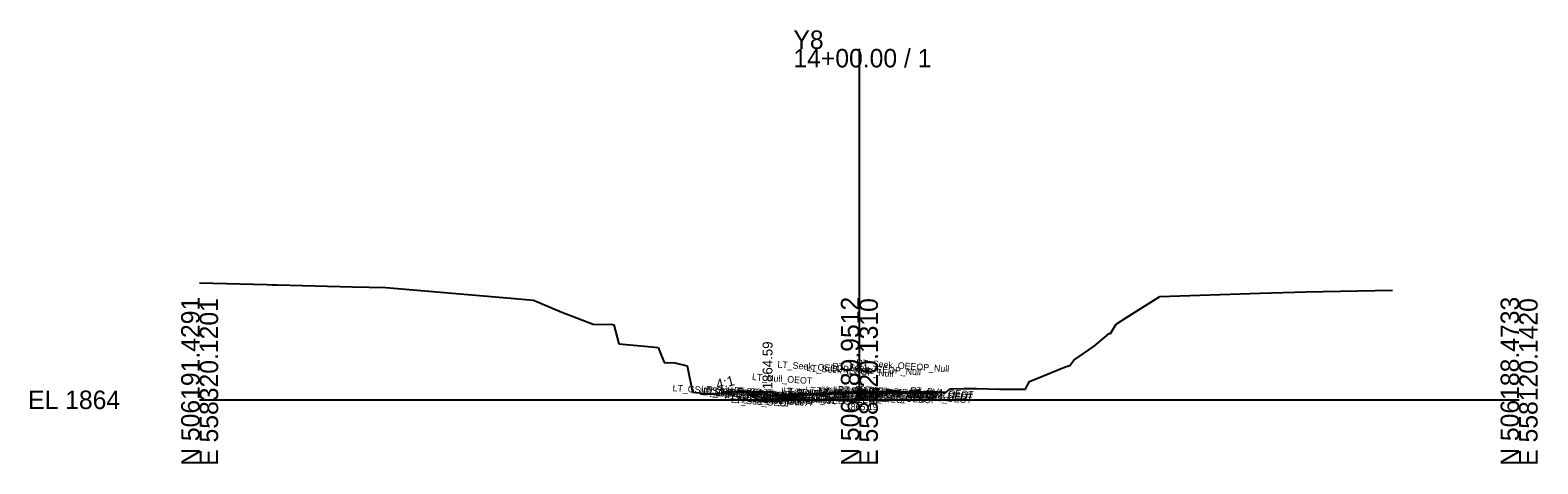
# Model space of a CAD drawing. Extents: x -26 to 203, y -10 to 8070.
# Drawn here: x -25.7 to 202.8, y 3990.3 to 4056 of the extents above; entities that cross this region are included whole.
import ezdxf

# ---------------------------------------------------------------- set-up
doc = ezdxf.new("R2010")
doc.units = 0
for name, color, linetype in [('Default', 7, 'Continuous'), ('Exist Cross Section Cell', 7, 'Continuous'), ('Exist XS Center Line Elevation Label', 7, 'Continuous'), ('Exist XS Ground Line', 7, 'Continuous'), ('Prop CMT Conc Surface', 7, 'Continuous'), ('Prop CMT Concrete Structures', 7, 'Continuous'), ('Prop CMT Pvmt Course 1', 7, 'Continuous'), ('Prop CMT Pvmt Course 1 CG', 7, 'Continuous'), ('Prop CMT Pvmt Course 2', 7, 'Continuous'), ('Prop CMT Pvmt Course 3', 7, 'Continuous'), ('Prop CMT Pvmt Surface', 7, 'Continuous'), ('Prop CMT Slope Grass', 7, 'Continuous'), ('Prop CMT Subgrade Earthwork', 7, 'Continuous'), ('Prop XS Earthwork Shape', 7, 'Continuous'), ('Prop XS Hydro Elevations', 7, 'Continuous'), ('Prop XS Side Slope Text', 7, 'Continuous'), ('Typical Text Grade Point CELL', 7, 'Continuous')]:
    doc.layers.add(name, color=color, linetype=linetype)

msp = doc.modelspace()

# ---------------------------------------------------------------- linework, layer by layer
at = {"layer": 'Exist Cross Section Cell'}
for p, q in [((100, 4000), (100, 4053.15)), ((0, 4000), (100, 4000)), ((100, 4000), (200, 4000))]:
    msp.add_line(p, q, dxfattribs=at)
at = {"layer": 'Exist XS Ground Line'}
for p, q in [((0, 4017.72), (10.19, 4017.45)), ((10.19, 4017.45), (10.97, 4017.44)), ((10.97, 4017.44), (11.82, 4017.4)), ((11.82, 4017.4), (23.17, 4017.13)), ((23.17, 4017.13), (28.21, 4017.02)), ((28.21, 4017.02), (47.17, 4015.4)), ((47.17, 4015.4), (50.61, 4015.12)), ((140.5, 4012.47), (144.99, 4015.32)), ((144.99, 4015.32), (145.55, 4015.67)), ((145.55, 4015.67), (160.74, 4016.15)), ((160.74, 4016.15), (167.65, 4016.36)), ((167.65, 4016.36), (180.8, 4016.61)), ((50.61, 4015.12), (54.88, 4013.3)), ((54.88, 4013.3), (59.66, 4011.45)), ((59.66, 4011.45), (61.57, 4011.42)), ((61.57, 4011.42), (62.45, 4011.45)), ((62.45, 4011.45), (62.76, 4011.35)), ((62.76, 4011.35), (63.56, 4008.5)), ((138.04, 4010.03), (138.9, 4011.45)), ((138.9, 4011.45), (140.5, 4012.47)), ((63.56, 4008.5), (68.55, 4008.02)), ((135.58, 4008.12), (137.85, 4010.05)), ((137.85, 4010.05), (138.04, 4010.03)), ((68.55, 4008.02), (69.51, 4007.92)), ((69.51, 4007.92), (70.41, 4005.64)), ((132.53, 4006.02), (135.58, 4008.12)), ((70.41, 4005.64), (72.03, 4005.6)), ((72.03, 4005.6), (73.88, 4005.14)), ((73.88, 4005.14), (74.71, 4001.18)), ((125.79, 4002.78), (131.35, 4005.04)), ((131.35, 4005.04), (131.89, 4005.22)), ((131.89, 4005.22), (132.53, 4006.02)), ((113.14, 4001.17), (113.7, 4001.66)), ((113.7, 4001.66), (115.81, 4001.7)), ((115.81, 4001.7), (117.76, 4001.74)), ((117.76, 4001.74), (121.22, 4001.62)), ((121.22, 4001.62), (125.16, 4001.59)), ((125.16, 4001.59), (125.48, 4002.24)), ((125.48, 4002.24), (125.79, 4002.78)), ((74.71, 4001.18), (75.72, 4001.08)), ((75.72, 4001.08), (76.93, 4000.86)), ((76.93, 4000.86), (78.99, 4001.01)), ((78.99, 4001.01), (81.67, 4001.31)), ((81.67, 4001.31), (83.1, 4001.28)), ((83.1, 4001.28), (86.56, 4001.19)), ((86.56, 4001.19), (87.31, 4000.72)), ((87.31, 4000.72), (88.45, 4000.76)), ((88.45, 4000.76), (88.89, 4000.77)), ((88.89, 4000.77), (98.67, 4001.13)), ((98.67, 4001.13), (100, 4001.19)), ((100, 4001.19), (100.56, 4001.21)), ((100.56, 4001.21), (101.8, 4001.21)), ((101.8, 4001.21), (111.47, 4001.18)), ((111.47, 4001.18), (112.32, 4001.18)), ((112.32, 4001.18), (113.14, 4001.17))]:
    msp.add_line(p, q, dxfattribs=at)
at = {"layer": 'Prop CMT Conc Surface'}
for points in [[(86.08, 4000.59), (86.08, 4001.09), (85.58, 4001.09)], [(88.08, 4000.74), (86.08, 4000.59)]]:
    msp.add_lwpolyline(points, dxfattribs=at)
at = {"layer": 'Prop CMT Concrete Structures'}
for points in [[(88.08, 4000.74), (86.08, 4000.59), (86.08, 4001.09), (85.58, 4001.09)], [(85.58, 4001.09), (85.58, 4000.07), (88.08, 4000.16)], [(88.08, 4000.16), (88.08, 4000.74)]]:
    msp.add_lwpolyline(points, dxfattribs=at)
at = {"layer": 'Prop CMT Pvmt Course 1'}
for points in [[(100, 4001.19), (98, 4001.11), (97.99, 4001.11), (94.01, 4000.96), (94, 4000.96), (88.08, 4000.74)], [(88.08, 4000.74), (88.08, 4000.49)], [(100, 4001.19), (102, 4001.21), (102.01, 4001.21), (105.99, 4001.2), (106, 4001.2), (111.92, 4001.18)]]:
    msp.add_lwpolyline(points, dxfattribs=at)
at = {"layer": 'Prop CMT Pvmt Course 1 CG'}
for points in [[(88.08, 4000.16), (85.08, 4000.05), (84.78, 3999.75)], [(84.78, 3999.75), (88.08, 3999.87)], [(88.08, 3999.87), (88.08, 4000.16)]]:
    msp.add_lwpolyline(points, dxfattribs=at)
at = {"layer": 'Prop CMT Pvmt Course 2'}
for points in [[(90.08, 4000.57), (88.08, 4000.49)], [(88.08, 4000.49), (88.08, 4000.24)], [(88.08, 4000.24), (90.08, 4000.32)]]:
    msp.add_lwpolyline(points, dxfattribs=at)
at = {"layer": 'Prop CMT Pvmt Course 3'}
for points in [[(90.08, 4000.32), (88.08, 4000.24)], [(88.08, 4000.24), (88.08, 3999.87)], [(88.08, 3999.87), (90.08, 3999.94)]]:
    msp.add_lwpolyline(points, dxfattribs=at)
at = {"layer": 'Prop CMT Pvmt Surface'}
for points in [[(100, 4001.19), (98, 4001.11), (97.99, 4001.11), (94.01, 4000.96), (94, 4000.96), (88.08, 4000.74)], [(100, 4001.19), (102, 4001.21), (102.01, 4001.21), (105.99, 4001.2), (106, 4001.2), (111.92, 4001.18)]]:
    msp.add_lwpolyline(points, dxfattribs=at)
at = {"layer": 'Prop CMT Slope Grass'}
msp.add_lwpolyline([(85.58, 4001.09), (80.08, 4001.2), (79.55, 4001.07)], dxfattribs=at)
at = {"layer": 'Prop CMT Subgrade Earthwork'}
for points in [[(88.08, 3999.87), (84.78, 3999.75), (83.39, 4001.13)], [(90.08, 3999.94), (88.08, 3999.87)], [(90.08, 3999.94), (90.08, 4000.82)]]:
    msp.add_lwpolyline(points, dxfattribs=at)
at = {"layer": 'Prop XS Earthwork Shape'}
for points in [[(80.08, 4001.2), (79.55, 4001.07), (80.63, 4001.19)], [(86.08, 4000.59), (86.08, 4001.09), (85.58, 4001.09), (83.39, 4001.13), (80.63, 4001.19), (81.67, 4001.31), (83.1, 4001.28), (86.56, 4001.19), (87.31, 4000.72)], [(86.08, 4000.59), (86.08, 4001.09), (85.58, 4001.09), (83.39, 4001.13), (84.78, 3999.75), (88.08, 3999.87), (90.08, 3999.94), (90.08, 4000.69), (100.1, 4001.07), (111.92, 4001.05), (111.92, 4001.18), (111.47, 4001.18), (105.99, 4001.2), (102, 4001.21), (100, 4001.19), (98.67, 4001.13), (98, 4001.11), (94.01, 4000.96), (88.89, 4000.77), (88.45, 4000.76), (88.08, 4000.74), (87.31, 4000.72)], [(100, 4001.19), (102, 4001.21), (101.8, 4001.21), (100.56, 4001.21)]]:
    msp.add_lwpolyline(points, close=True, dxfattribs=at)

# ---------------------------------------------------------------- texts
at = {"layer": 'Default'}
msp.add_text('-', height=0.0001, dxfattribs=at).set_placement((0, 4000))
at = {"layer": 'Exist Cross Section Cell'}
for s, p in [('Y8', (90, 4053.15)), ('14+00.00 / 1', (90, 4050.35)), ('EL 1864', (-26, 3998.6))]:
    msp.add_text(s, height=2.8, dxfattribs=at).set_placement(p)
for s, p in [('N 506191.4291', (0, 3990)), ('N 506189.9512', (100, 3990)), ('N 506188.4733', (200, 3990)), ('E 558320.1201', (2.8, 3990)), ('E 558220.1310', (102.8, 3990)), ('E 558120.1420', (202.8, 3990))]:
    msp.add_text(s, height=2.8, rotation=90, dxfattribs=at).set_placement(p)
at = {"layer": 'Exist XS Center Line Elevation Label'}
msp.add_text('1865.19', height=1, dxfattribs=at).set_placement((97.94, 3998.44))
at = {"layer": 'Prop XS Hydro Elevations'}
msp.add_text('1864.59', height=1.5, rotation=90, dxfattribs=at).set_placement((86.83, 4001.59))
at = {"layer": 'Prop XS Side Slope Text'}
msp.add_text('4:1', height=1.5, rotation=14.0359, dxfattribs=at).set_placement((78.48, 4001.57))
at = {"layer": 'Typical Text Grade Point CELL'}
for s, p in [('LT_Null_OEOT', (83.7, 4003)), ('LT_Seek_OEEOP_Null', (87.55, 4004.89)), ('LT_Seek_IEEOP_Null', (91.93, 4004.37)), ('RT_Seek_IEEOP_Null', (95.87, 4004.62)), ('RT_Seek_OEEOP_Null', (99.49, 4005.15)), ('LT_GS_OS_GR_Face_Graphics', (71.66, 4001.32)), ('LT_Slope_Fill', (75.77, 4000.83)), ('LT_Sub_Trench_Out_DLT', (76.02, 4001.15)), ('LT_GS_OS_GR_Face_Graphics1', (76.26, 4000.73)), ('LT_CSLP_Pnt', (76.35, 4000.96)), ('LT_CG_MatchPVSlope_Null', (78.01, 4000.73)), ('LT_CG_Top_BOC', (80.46, 4000.95)), ('LT_CG_Top_Face', (80.98, 4000.95)), ('LT_PV_Sub_Tie_Out', (88.14, 4000.87)), ('LT_Null OEEOP Test', (88.4, 4000.9)), ('LT_PV1_OEEOP', (89.49, 4000.65)), ('LT_Pvmt Out', (90.25, 4000.72)), ('LT_Null IEEOP Test', (91.78, 4000.99)), ('LT_PV_Sub_Tie_In', (92.75, 4000.97)), ('LT_PV2_IEEOP', (93.75, 4000.66)), ('LT_PV1_IEEOP', (93.87, 4000.78)), ('Null RT Pvmt Slope', (94.26, 4001.11)), ('Null LT Pvmt Slope', (94.32, 4001.08)), ('PV1_Overlay_Null', (94.75, 4000.93)), ('LT_Pvmt In', (94.84, 4000.83)), ('RT_PV_Sub_Tie_In', (96.7, 4001.08)), ('RT_Null IEEOP Test', (96.72, 4001.11)), ('PV2_PGL', (97.32, 4000.62)), ('PV1_PGL', (97.44, 4000.87)), ('RT_PV2_IEEOP', (97.69, 4000.74)), ('RT_PV1_IEEOP', (97.81, 4000.85)), ('RT_Pvmt In', (98.8, 4000.93)), ('CL', (99.2, 4000.75)), ('RT_Null OEEOP Test', (99.34, 4001.13)), ('RT_PV_Sub_Tie_Out', (100.08, 4001.11)), ('RT_PV2_OEEOP', (101.31, 4000.76)), ('RT_PV1_OEEOP', (101.43, 4000.88)), ('RT_Pvmt Out', (102.17, 4000.96)), ('RT_PV2_OEOT', (107.58, 4000.73)), ('RT_PV1_OEOT', (107.7, 4000.97)), ('LT_CG1_Shelf_Out', (79.55, 3999.94)), ('LT_Sub_OEOP', (80.52, 3999.54)), ('LT_CG_Bot_BOC', (80.6, 3999.91)), ('LT_CG_Top_Gut', (81.24, 4000.43)), ('LT_PV2_OEOT', (83.8, 4000.29)), ('LT_PV3_OEOT', (83.8, 4000.04)), ('LT_Sub_OEOT', (83.82, 3999.67)), ('LT_PV1_OEOT', (83.92, 4000.53)), ('LT_CG_Bot_IE', (83.98, 3999.95)), ('LT_PV2_OEEOP', (89.37, 4000.54)), ('LT_PV3_OEEOP', (89.37, 4000.29)), ('LT_Sub_OEEOP', (89.39, 3999.91)), ('LT_PV3_IEEOP', (93.75, 4000.41)), ('LT_Sub_IEEOP', (93.77, 4000.03)), ('Sub_PGL', (97.34, 4000)), ('PV3_PGL', (97.32, 4000.37)), ('RT_PV3_IEEOP', (97.69, 4000.49)), ('RT_Sub_IEEOP', (97.71, 4000.11)), ('RT_PV3_OEEOP', (101.31, 4000.51)), ('RT_Sub_OEEOP', (101.33, 4000.13)), ('RT_PV3_OEOT', (107.58, 4000.48)), ('RT_Sub_OEOT', (107.6, 4000.11))]:
    msp.add_text(s, height=1, rotation=356, dxfattribs=at).set_placement(p)

doc.saveas('drawing.dxf')
